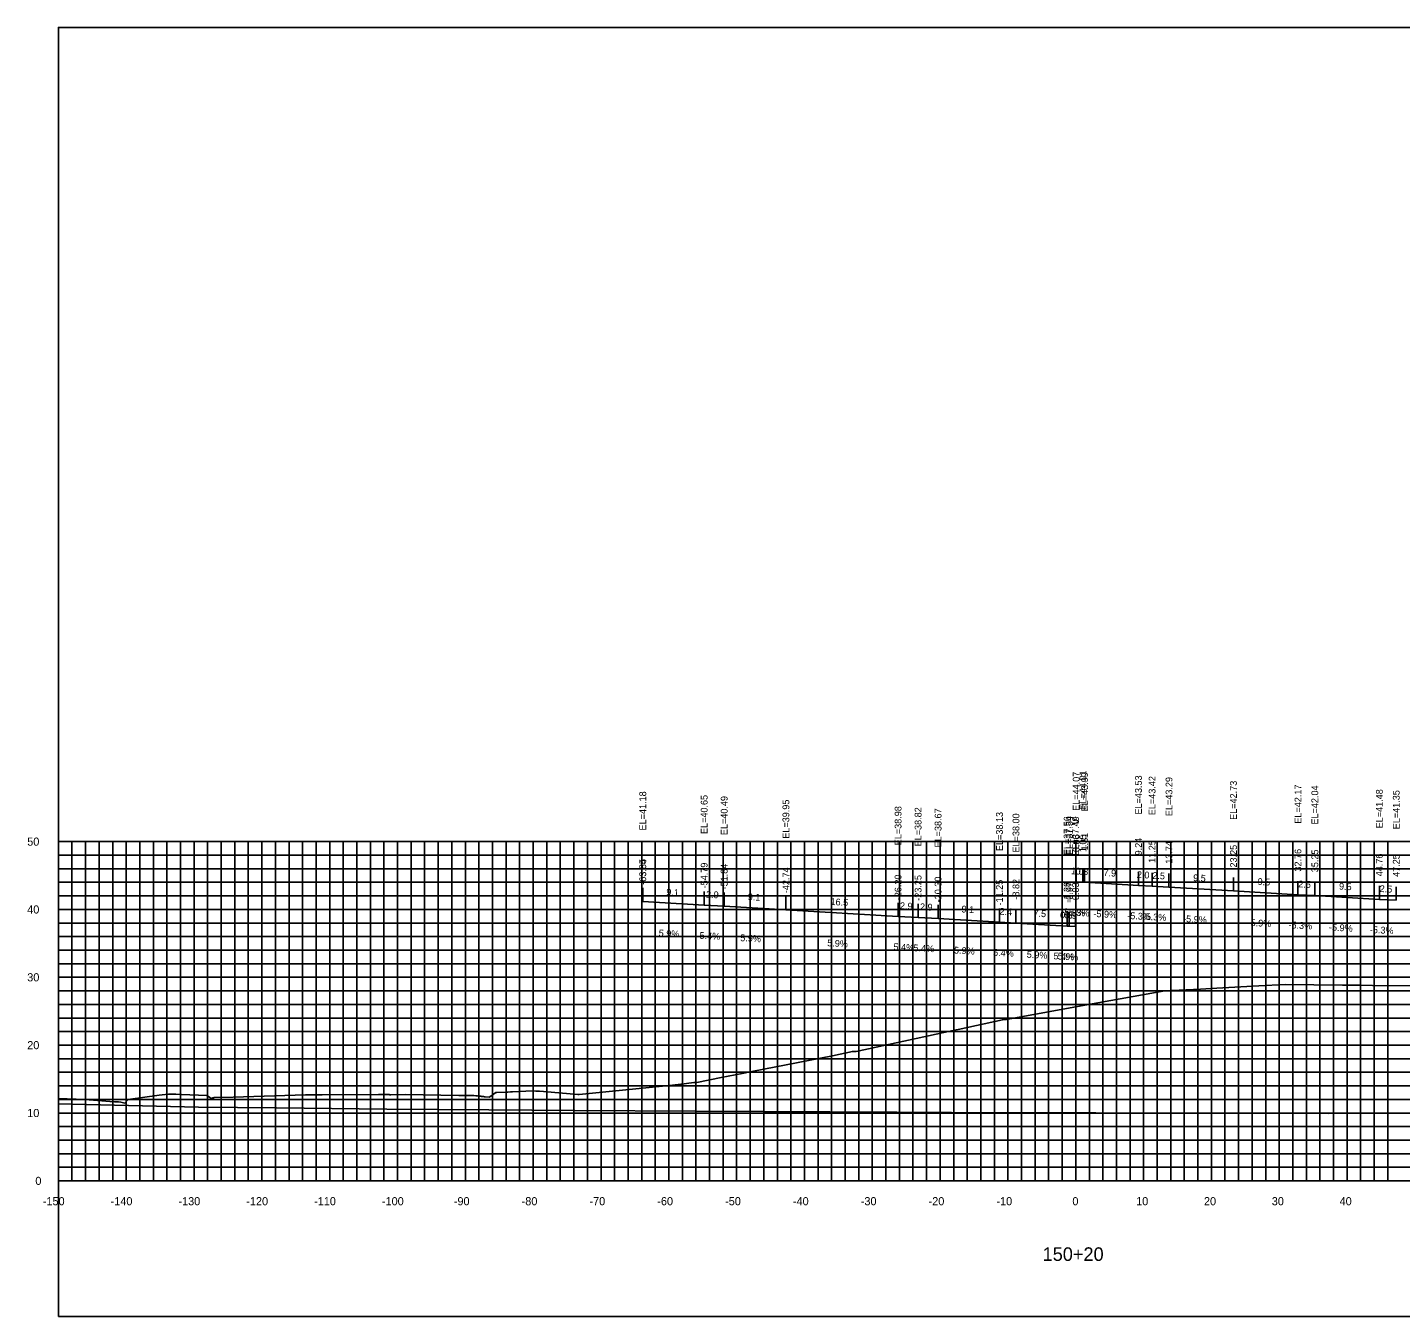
# Model space of a CAD drawing. Extents: x 1800880 to 1818864, y 245271 to 250560.
# Drawn here: x 1810963.5 to 1811165.9, y 247840 to 248030 of the extents above; entities that cross this region are included whole.
import ezdxf

# ---------------------------------------------------------------- set-up
doc = ezdxf.new("R2010")
doc.units = 0
for name, color, linetype in [('33', 7, 'Continuous'), ('ANNO-TXT', 7, 'Continuous'), ('AXIS', 7, 'Continuous'), ('CL-CNST', 7, 'Continuous'), ('DESIGN - DRAINAGE - Bridges', 7, 'Continuous'), ('Level 32', 7, 'Continuous'), ('Level 37', 7, 'Continuous'), ('Level 46', 7, 'Continuous'), ('Level 62', 7, 'Continuous'), ('SHT-BDR', 7, 'Continuous')]:
    doc.layers.add(name, color=color, linetype=linetype)

msp = doc.modelspace()

# ---------------------------------------------------------------- linework, layer by layer
at = {"layer": 'AXIS'}
msp.add_lwpolyline([(1811118.12, 247904.06), (1811119.11, 247904), (1811119.37, 247903.99), (1811127.3, 247903.52), (1811129.31, 247903.41), (1811131.8, 247903.28), (1811141.31, 247902.72), (1811150.82, 247902.16), (1811153.31, 247902.03), (1811162.82, 247901.47), (1811165.31, 247901.34)], dxfattribs=at)
at = {"layer": 'CL-CNST'}
msp.add_lwpolyline([(1810968.06, 247872.13), (1810971.94, 247871.97), (1810974.46, 247871.78), (1810975.62, 247871.69), (1810976.34, 247871.64), (1810976.49, 247871.63), (1810976.9, 247871.63), (1810977.24, 247871.6), (1810977.87, 247871.45), (1810977.91, 247871.51), (1810978.32, 247872), (1810982.92, 247872.62), (1810983.34, 247872.67), (1810984.29, 247872.78), (1810984.66, 247872.78), (1810984.79, 247872.78), (1810985.37, 247872.76), (1810986.2, 247872.73), (1810989.93, 247872.56), (1810990.36, 247872.3), (1810990.6, 247872.15), (1810990.85, 247872.21), (1810990.92, 247872.23), (1810991.02, 247872.26), (1810993.83, 247872.34), (1811004.5, 247872.66), (1811006.94, 247872.68), (1811015.25, 247872.73), (1811015.42, 247872.73), (1811016.23, 247872.73), (1811016.25, 247872.72), (1811016.4, 247872.72), (1811016.53, 247872.71), (1811016.64, 247872.7), (1811016.74, 247872.7), (1811016.82, 247872.7), (1811016.9, 247872.69), (1811016.97, 247872.69), (1811017.03, 247872.69), (1811017.08, 247872.68), (1811019.17, 247872.71), (1811027.08, 247872.59), (1811028.08, 247872.58), (1811029.32, 247872.56), (1811029.62, 247872.52), (1811029.87, 247872.5), (1811030.06, 247872.48), (1811030.21, 247872.46), (1811030.34, 247872.45), (1811030.44, 247872.43), (1811030.53, 247872.42), (1811030.61, 247872.42), (1811030.67, 247872.41), (1811030.73, 247872.4), (1811030.78, 247872.4), (1811030.83, 247872.39), (1811030.87, 247872.39), (1811030.9, 247872.38), (1811030.94, 247872.38), (1811030.96, 247872.38), (1811030.99, 247872.37), (1811031.56, 247872.32), (1811031.66, 247872.38), (1811032.21, 247872.79), (1811032.53, 247873.02), (1811032.54, 247873.03), (1811032.69, 247873.03), (1811032.7, 247873.03), (1811034.02, 247873.07), (1811034.32, 247873.07), (1811034.74, 247873.11), (1811035.03, 247873.12), (1811037.94, 247873.24), (1811038.02, 247873.24), (1811038.43, 247873.23), (1811039.01, 247873.22), (1811039.56, 247873.15), (1811044.64, 247872.74), (1811044.83, 247872.74), (1811058.59, 247874.08), (1811059.82, 247874.24), (1811059.98, 247874.26), (1811060.68, 247874.35), (1811061.75, 247874.49), (1811061.76, 247874.5), (1811062.19, 247874.49), (1811062.21, 247874.49), (1811065.76, 247875.2), (1811068.85, 247875.81), (1811070.32, 247876.1), (1811082.2, 247878.44), (1811085.12, 247879.07), (1811085.6, 247879.08), (1811085.7, 247879.08), (1811100.43, 247882.25), (1811100.73, 247882.3), (1811107.25, 247883.74), (1811107.62, 247883.75), (1811107.83, 247883.76), (1811108.11, 247883.83), (1811119.95, 247885.98), (1811131.2, 247887.98), (1811136.43, 247888.25), (1811138.85, 247888.38), (1811145.05, 247888.72), (1811148.94, 247888.93), (1811157.41, 247888.84), (1811160.02, 247888.82), (1811161.8, 247888.8), (1811171.45, 247888.71)], dxfattribs=at)
at = {"layer": 'DESIGN - DRAINAGE - Bridges'}
for p, q in [((1810968, 247909.99), (1810968.06, 247909.99)), ((1810968.06, 247859.99), (1810968.06, 247909.99)), ((1810968, 247899.99), (1810968.06, 247899.99)), ((1810968, 247889.99), (1810968.06, 247889.99)), ((1810968, 247879.99), (1810968.06, 247879.99)), ((1810968, 247869.99), (1810968.06, 247869.99)), ((1810968, 247859.99), (1810968.06, 247859.99)), ((1810968.06, 247859.99), (1811268.06, 247859.99)), ((1810968.06, 247859.93), (1810968.06, 247859.99)), ((1810978.06, 247859.93), (1810978.06, 247859.99)), ((1810988.06, 247859.93), (1810988.06, 247859.99)), ((1810998.06, 247859.93), (1810998.06, 247859.99)), ((1811008.06, 247859.93), (1811008.06, 247859.99)), ((1811018.06, 247859.93), (1811018.06, 247859.99)), ((1811028.06, 247859.93), (1811028.06, 247859.99)), ((1811038.06, 247859.93), (1811038.06, 247859.99)), ((1811048.06, 247859.93), (1811048.06, 247859.99)), ((1811058.06, 247859.93), (1811058.06, 247859.99)), ((1811068.06, 247859.93), (1811068.06, 247859.99)), ((1811078.06, 247859.93), (1811078.06, 247859.99)), ((1811088.06, 247859.93), (1811088.06, 247859.99)), ((1811098.06, 247859.93), (1811098.06, 247859.99)), ((1811108.06, 247859.93), (1811108.06, 247859.99)), ((1811118.06, 247859.93), (1811118.06, 247859.99)), ((1811128.06, 247859.93), (1811128.06, 247859.99)), ((1811138.06, 247859.93), (1811138.06, 247859.99)), ((1811148.06, 247859.93), (1811148.06, 247859.99)), ((1811158.06, 247859.93), (1811158.06, 247859.99))]:
    msp.add_line(p, q, dxfattribs=at)
at = {"layer": 'Level 37'}
for p, q in [((1811118.12, 247904.06), (1811118.12, 247906.06)), ((1811119.11, 247904), (1811119.11, 247906)), ((1811119.37, 247903.99), (1811119.37, 247905.99)), ((1811127.3, 247903.52), (1811127.3, 247905.52)), ((1811129.31, 247903.41), (1811129.31, 247905.41)), ((1811131.8, 247903.28), (1811131.8, 247905.28)), ((1811141.31, 247902.72), (1811141.31, 247904.72)), ((1811054.21, 247901.17), (1811054.21, 247903.17)), ((1811054.22, 247901.17), (1811054.22, 247903.17)), ((1811063.27, 247900.64), (1811063.27, 247902.64)), ((1811066.22, 247900.48), (1811066.22, 247902.48)), ((1811150.82, 247902.16), (1811150.82, 247904.16)), ((1811153.31, 247902.03), (1811153.31, 247904.03)), ((1811162.82, 247901.47), (1811162.82, 247903.47)), ((1811165.31, 247901.34), (1811165.31, 247903.34)), ((1811075.32, 247899.95), (1811075.32, 247901.95)), ((1811091.86, 247898.97), (1811091.86, 247900.97)), ((1811094.81, 247898.82), (1811094.81, 247900.82)), ((1811097.76, 247898.66), (1811097.76, 247900.66)), ((1811106.81, 247898.13), (1811106.81, 247900.13)), ((1811109.24, 247897.99), (1811109.24, 247899.99)), ((1811116.79, 247897.55), (1811116.79, 247899.55)), ((1811117.09, 247897.54), (1811117.09, 247899.54)), ((1811118.03, 247897.48), (1811118.03, 247899.48))]:
    msp.add_line(p, q, dxfattribs=at)
msp.add_lwpolyline([(1810968.06, 247839.99), (1811268.06, 247839.99), (1811268.06, 248029.99), (1810968.06, 248029.99)], close=True, dxfattribs=at)
at = {"layer": 'Level 46'}
for p, q in [((1810968.06, 247909.99), (1811268.06, 247909.99)), ((1810968.06, 247859.99), (1810968.06, 247909.99)), ((1810970.06, 247859.99), (1810970.06, 247909.99)), ((1810972.06, 247859.99), (1810972.06, 247909.99)), ((1810974.06, 247859.99), (1810974.06, 247909.99)), ((1810976.06, 247859.99), (1810976.06, 247909.99)), ((1810978.06, 247859.99), (1810978.06, 247909.99)), ((1810980.06, 247859.99), (1810980.06, 247909.99)), ((1810982.06, 247859.99), (1810982.06, 247909.99)), ((1810984.06, 247859.99), (1810984.06, 247909.99)), ((1810986.06, 247859.99), (1810986.06, 247909.99)), ((1810988.06, 247859.99), (1810988.06, 247909.99)), ((1810990.06, 247859.99), (1810990.06, 247909.99)), ((1810992.06, 247859.99), (1810992.06, 247909.99)), ((1810994.06, 247859.99), (1810994.06, 247909.99)), ((1810996.06, 247859.99), (1810996.06, 247909.99)), ((1810998.06, 247859.99), (1810998.06, 247909.99)), ((1811000.06, 247859.99), (1811000.06, 247909.99)), ((1811002.06, 247859.99), (1811002.06, 247909.99)), ((1811004.06, 247859.99), (1811004.06, 247909.99)), ((1811006.06, 247859.99), (1811006.06, 247909.99)), ((1811008.06, 247859.99), (1811008.06, 247909.99)), ((1811010.06, 247859.99), (1811010.06, 247909.99)), ((1811012.06, 247859.99), (1811012.06, 247909.99)), ((1811014.06, 247859.99), (1811014.06, 247909.99)), ((1811016.06, 247859.99), (1811016.06, 247909.99)), ((1811018.06, 247859.99), (1811018.06, 247909.99)), ((1811020.06, 247859.99), (1811020.06, 247909.99)), ((1811022.06, 247859.99), (1811022.06, 247909.99)), ((1811024.06, 247859.99), (1811024.06, 247909.99)), ((1811026.06, 247859.99), (1811026.06, 247909.99)), ((1811028.06, 247859.99), (1811028.06, 247909.99)), ((1811030.06, 247859.99), (1811030.06, 247909.99)), ((1811032.06, 247859.99), (1811032.06, 247909.99)), ((1811034.06, 247859.99), (1811034.06, 247909.99)), ((1811036.06, 247859.99), (1811036.06, 247909.99)), ((1811038.06, 247859.99), (1811038.06, 247909.99)), ((1811040.06, 247859.99), (1811040.06, 247909.99)), ((1811042.06, 247859.99), (1811042.06, 247909.99)), ((1811044.06, 247859.99), (1811044.06, 247909.99)), ((1811046.06, 247859.99), (1811046.06, 247909.99)), ((1811048.06, 247859.99), (1811048.06, 247909.99)), ((1811050.06, 247859.99), (1811050.06, 247909.99)), ((1811052.06, 247859.99), (1811052.06, 247909.99)), ((1811054.06, 247859.99), (1811054.06, 247909.99)), ((1811056.06, 247859.99), (1811056.06, 247909.99)), ((1811058.06, 247859.99), (1811058.06, 247909.99)), ((1811060.06, 247859.99), (1811060.06, 247909.99)), ((1811062.06, 247859.99), (1811062.06, 247909.99)), ((1811064.06, 247859.99), (1811064.06, 247909.99)), ((1811066.06, 247859.99), (1811066.06, 247909.99)), ((1811068.06, 247859.99), (1811068.06, 247909.99)), ((1811070.06, 247859.99), (1811070.06, 247909.99)), ((1811072.06, 247859.99), (1811072.06, 247909.99)), ((1811074.06, 247859.99), (1811074.06, 247909.99)), ((1811076.06, 247859.99), (1811076.06, 247909.99)), ((1811078.06, 247859.99), (1811078.06, 247909.99)), ((1811080.06, 247859.99), (1811080.06, 247909.99)), ((1811082.06, 247859.99), (1811082.06, 247909.99)), ((1811084.06, 247859.99), (1811084.06, 247909.99)), ((1811086.06, 247859.99), (1811086.06, 247909.99)), ((1811088.06, 247859.99), (1811088.06, 247909.99)), ((1811090.06, 247859.99), (1811090.06, 247909.99)), ((1811092.06, 247859.99), (1811092.06, 247909.99)), ((1811094.06, 247859.99), (1811094.06, 247909.99)), ((1811096.06, 247859.99), (1811096.06, 247909.99)), ((1811098.06, 247859.99), (1811098.06, 247909.99)), ((1811100.06, 247859.99), (1811100.06, 247909.99)), ((1811102.06, 247859.99), (1811102.06, 247909.99)), ((1811104.06, 247859.99), (1811104.06, 247909.99)), ((1811106.06, 247859.99), (1811106.06, 247909.99)), ((1811108.06, 247859.99), (1811108.06, 247909.99)), ((1811110.06, 247859.99), (1811110.06, 247909.99)), ((1811112.06, 247859.99), (1811112.06, 247909.99)), ((1811114.06, 247859.99), (1811114.06, 247909.99)), ((1811116.06, 247859.99), (1811116.06, 247909.99)), ((1811118.06, 247859.99), (1811118.06, 247909.99)), ((1811120.06, 247859.99), (1811120.06, 247909.99)), ((1811122.06, 247859.99), (1811122.06, 247909.99)), ((1811124.06, 247859.99), (1811124.06, 247909.99)), ((1811126.06, 247859.99), (1811126.06, 247909.99)), ((1811128.06, 247859.99), (1811128.06, 247909.99)), ((1811130.06, 247859.99), (1811130.06, 247909.99)), ((1811132.06, 247859.99), (1811132.06, 247909.99)), ((1811134.06, 247859.99), (1811134.06, 247909.99)), ((1811136.06, 247859.99), (1811136.06, 247909.99)), ((1811138.06, 247859.99), (1811138.06, 247909.99)), ((1811140.06, 247859.99), (1811140.06, 247909.99)), ((1811142.06, 247859.99), (1811142.06, 247909.99)), ((1811144.06, 247859.99), (1811144.06, 247909.99)), ((1811146.06, 247859.99), (1811146.06, 247909.99)), ((1811148.06, 247859.99), (1811148.06, 247909.99)), ((1811150.06, 247859.99), (1811150.06, 247909.99)), ((1811152.06, 247859.99), (1811152.06, 247909.99)), ((1811154.06, 247859.99), (1811154.06, 247909.99)), ((1811156.06, 247859.99), (1811156.06, 247909.99)), ((1811158.06, 247859.99), (1811158.06, 247909.99)), ((1811160.06, 247859.99), (1811160.06, 247909.99)), ((1811162.06, 247859.99), (1811162.06, 247909.99)), ((1811164.06, 247859.99), (1811164.06, 247909.99)), ((1810968.06, 247907.99), (1811268.06, 247907.99)), ((1810968.06, 247905.99), (1811268.06, 247905.99)), ((1810968.06, 247903.99), (1811268.06, 247903.99)), ((1810968.06, 247901.99), (1811268.06, 247901.99)), ((1810968.06, 247899.99), (1811268.06, 247899.99)), ((1810968.06, 247897.99), (1811268.06, 247897.99)), ((1810968.06, 247895.99), (1811268.06, 247895.99)), ((1810968.06, 247893.99), (1811268.06, 247893.99)), ((1810968.06, 247891.99), (1811268.06, 247891.99)), ((1810968.06, 247889.99), (1811268.06, 247889.99)), ((1810968.06, 247887.99), (1811268.06, 247887.99)), ((1810968.06, 247885.99), (1811268.06, 247885.99)), ((1810968.06, 247883.99), (1811268.06, 247883.99)), ((1810968.06, 247881.99), (1811268.06, 247881.99)), ((1810968.06, 247879.99), (1811268.06, 247879.99)), ((1810968.06, 247877.99), (1811268.06, 247877.99)), ((1810968.06, 247875.99), (1811268.06, 247875.99)), ((1810968.06, 247873.99), (1811268.06, 247873.99)), ((1810968.06, 247871.99), (1811268.06, 247871.99)), ((1810968.06, 247869.99), (1811268.06, 247869.99)), ((1810968.06, 247867.99), (1811268.06, 247867.99)), ((1810968.06, 247865.99), (1811268.06, 247865.99)), ((1810968.06, 247863.99), (1811268.06, 247863.99)), ((1810968.06, 247861.99), (1811268.06, 247861.99)), ((1810968.06, 247859.99), (1811268.06, 247859.99))]:
    msp.add_line(p, q, dxfattribs=at)
at = {"layer": 'Level 62'}
for points in [[(1811054.21, 247901.17), (1811054.22, 247901.17), (1811063.27, 247900.64), (1811066.22, 247900.48), (1811075.32, 247899.95), (1811091.86, 247898.97), (1811094.81, 247898.82), (1811097.76, 247898.66), (1811106.81, 247898.13), (1811109.24, 247897.99), (1811116.79, 247897.55), (1811117.09, 247897.54), (1811118.03, 247897.48)], [(1810968.06, 247871.33), (1810988.71, 247870.86), (1811000.23, 247870.77), (1811016.47, 247870.57), (1811031.54, 247870.47), (1811044.22, 247870.35), (1811061.92, 247870.26), (1811071.98, 247870.19), (1811091.69, 247870.12), (1811099.73, 247870.05), (1811121.03, 247870.01), (1811127.49, 247869.97), (1811150.08, 247869.97), (1811155.25, 247869.93), (1811178.9, 247869.97), (1811183, 247869.94), (1811207.56, 247870.02), (1811210.76, 247870.01), (1811236.08, 247870.13), (1811238.51, 247870.13), (1811264.5, 247870.28), (1811266.27, 247870.24), (1811268.06, 247870.26)]]:
    msp.add_lwpolyline(points, dxfattribs=at)

# ---------------------------------------------------------------- texts
for s, p in [('-150', (1810965.76, 247856.39)), ('-140', (1810975.76, 247856.39)), ('-130', (1810985.76, 247856.39)), ('-120', (1810995.76, 247856.39)), ('-110', (1811005.76, 247856.39)), ('-100', (1811015.76, 247856.39)), ('-90', (1811026.36, 247856.39)), ('-80', (1811036.36, 247856.39)), ('-70', (1811046.36, 247856.39)), ('-60', (1811056.36, 247856.39)), ('-50', (1811066.36, 247856.39)), ('-40', (1811076.36, 247856.39)), ('-30', (1811086.36, 247856.39)), ('-20', (1811096.36, 247856.39)), ('-10', (1811106.36, 247856.39)), ('0', (1811117.56, 247856.39)), ('10', (1811126.96, 247856.39)), ('20', (1811136.96, 247856.39)), ('30', (1811146.96, 247856.39)), ('40', (1811156.96, 247856.39))]:
    msp.add_text(s, height=1.2).set_placement(p)
at = {"layer": '33'}
for s, p in [('50', (1810963.46, 247909.39)), ('40', (1810963.46, 247899.39)), ('30', (1810963.46, 247889.39)), ('20', (1810963.46, 247879.39)), ('10', (1810963.46, 247869.39)), ('0', (1810964.66, 247859.39))]:
    msp.add_text(s, height=1.2, dxfattribs=at).set_placement(p)
at = {"layer": 'ANNO-TXT'}
for s, rotation, p in [('1.0', 356.6368, (1811117.36, 247905.2)), ('0.3', 356.9763, (1811118.02, 247905.16)), ('7.9', 356.6368, (1811122.12, 247904.93)), ('2.0', 356.9763, (1811127.04, 247904.64)), ('2.5', 356.9763, (1811129.33, 247904.51)), ('9.5', 356.6368, (1811135.34, 247904.18)), ('9.5', 356.6368, (1811144.85, 247903.62)), ('2.5', 356.9763, (1811150.84, 247903.26)), ('9.1', 356.6368, (1811057.66, 247902.07)), ('2.9', 356.9238, (1811063.53, 247901.73)), ('9.1', 356.6368, (1811069.68, 247901.38)), ('9.5', 356.6368, (1811156.85, 247902.93)), ('2.5', 356.9763, (1811162.84, 247902.57)), ('16.5', 356.6368, (1811081.88, 247900.66)), ('2.9', 356.9238, (1811092.11, 247900.06)), ('2.9', 356.9238, (1811095.06, 247899.9)), ('9.1', 356.6368, (1811101.19, 247899.56)), ('2.4', 356.9238, (1811106.8, 247899.23)), ('7.5', 356.6368, (1811111.8, 247898.95)), ('0.3', 356.9238, (1811115.72, 247898.71)), ('-5.9%', 356.6368, (1811115.92, 247899.18)), ('0.9', 356.6368, (1811116.34, 247898.68)), ('-5.3%', 356.9763, (1811116.57, 247899.13)), ('-5.9%', 356.6368, (1811120.64, 247898.9)), ('-5.3%', 356.9763, (1811125.63, 247898.6)), ('-5.3%', 356.9763, (1811127.89, 247898.48)), ('-5.9%', 356.6368, (1811133.86, 247898.15)), ('-5.9%', 356.6368, (1811143.37, 247897.59)), ('-5.3%', 356.9763, (1811149.4, 247897.23)), ('5.9%', 356.6368, (1811056.54, 247896.03)), ('5.4%', 356.9238, (1811062.57, 247895.67)), ('5.9%', 356.6368, (1811068.57, 247895.33)), ('-5.9%', 356.6368, (1811155.37, 247896.9)), ('-5.3%', 356.9763, (1811161.4, 247896.54)), ('5.9%', 356.6368, (1811081.39, 247894.58)), ('5.4%', 356.9238, (1811091.16, 247894.01)), ('5.4%', 356.9238, (1811094.11, 247893.85)), ('5.9%', 356.6368, (1811100.08, 247893.51)), ('5.4%', 356.9238, (1811105.85, 247893.17)), ('5.9%', 356.6368, (1811110.81, 247892.89)), ('5.4%', 356.9238, (1811114.76, 247892.65)), ('5.9%', 356.6368, (1811115.36, 247892.63))]:
    msp.add_text(s, height=1, rotation=rotation, dxfattribs=at).set_placement(p)
at = {"layer": 'DESIGN - DRAINAGE - Bridges'}
for s, height, p in [('>', 1.5, (1811117.45, 247912.24)), ('-', 0.0001, (1810968.06, 247859.99))]:
    msp.add_text(s, height=height, dxfattribs=at).set_placement(p)
at = {"layer": 'Level 32'}
msp.add_text('150+20', height=2, dxfattribs=at).set_placement((1811113.17, 247848.19))
at = {"layer": 'SHT-BDR'}
for s, p in [('EL=44.07', (1811118.62, 247914.53)), ('EL=44.01', (1811119.61, 247914.72)), ('EL=43.99', (1811119.87, 247914.46)), ('EL=43.53', (1811127.8, 247913.99)), ('EL=43.42', (1811129.81, 247913.89)), ('EL=43.29', (1811132.3, 247913.75)), ('EL=42.73', (1811141.81, 247913.2)), ('EL=41.18', (1811054.71, 247911.64)), ('EL=41.18', (1811054.72, 247911.64)), ('EL=40.65', (1811063.77, 247911.11)), ('EL=40.49', (1811066.72, 247910.95)), ('EL=42.17', (1811151.32, 247912.64)), ('EL=42.04', (1811153.81, 247912.51)), ('EL=41.48', (1811163.32, 247911.95)), ('EL=41.35', (1811165.81, 247911.81)), ('EL=39.95', (1811075.82, 247910.42)), ('EL=38.98', (1811092.36, 247909.45)), ('EL=38.82', (1811095.31, 247909.29)), ('EL=38.67', (1811098.26, 247909.13)), ('EL=38.13', (1811107.31, 247908.6)), ('EL=38.00', (1811109.74, 247908.39)), ('EL=37.56', (1811117.29, 247907.98)), ('EL=37.54', (1811117.59, 247908.01)), ('EL=37.49', (1811118.53, 247907.95)), ('0.06', (1811118.62, 247908.45)), ('1.05', (1811119.61, 247908.44)), ('1.31', (1811119.87, 247908.68)), ('9.24', (1811127.8, 247907.96)), ('11.25', (1811129.81, 247906.86)), ('13.74', (1811132.3, 247906.73)), ('23.25', (1811141.81, 247906.17)), ('32.76', (1811151.32, 247905.57)), ('35.25', (1811153.81, 247905.48)), ('-63.85', (1811054.71, 247903.63)), ('-63.84', (1811054.72, 247903.63)), ('-54.79', (1811063.77, 247903.1)), ('-51.84', (1811066.72, 247902.94)), ('44.76', (1811163.32, 247904.88)), ('47.25', (1811165.81, 247904.79)), ('-42.74', (1811075.82, 247902.4)), ('-26.20', (1811092.36, 247901.35)), ('-23.25', (1811095.31, 247901.27)), ('-20.30', (1811098.26, 247901.04)), ('-11.25', (1811107.31, 247900.58)), ('-8.82', (1811109.74, 247901.44)), ('-1.28', (1811117.29, 247901)), ('-0.97', (1811117.59, 247900.98)), ('-0.03', (1811118.53, 247900.93))]:
    msp.add_text(s, height=1, rotation=90, dxfattribs=at).set_placement(p)

doc.saveas('drawing.dxf')
